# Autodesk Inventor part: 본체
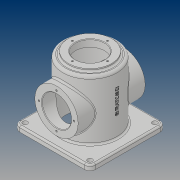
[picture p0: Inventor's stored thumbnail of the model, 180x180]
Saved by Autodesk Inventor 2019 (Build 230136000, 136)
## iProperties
Created: 2019-03
Part Number: 본체
Material: 일반
Document SubType Name: Modeling
Designer: PC312-13
Density: 1 g/cm^3
Appearance: 기본값
Author: PC312-13
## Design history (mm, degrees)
sketch "스케치1"
  geometry: C1 r 50 at (0, 0); 1 further point
  constraints: 1 centre point, 1 coincident
  dimensions: "d0" = 100 diameter of C1
extrude "돌출1" new body sketch "스케치1" distance "d1" = 120; taper "d2" = 0 deg
sketch "스케치2"
  geometry: C1 r 45 at (0, 0); 1 further point
  constraints: 1 centre point, 1 coincident
  dimensions: "d3" = 90 diameter of C1
extrude "돌출2" cut sketch "스케치2" distance "d4" = 112; taper "d5" = 0 deg
sketch "스케치3"
  geometry: L1 (-70, -70)-(70, -70); L2 (70, -70)-(70, 70); L3 (70, 70)-(-70, 70); L4 (-70, 70)-(-70, -70); L5 (-70, -70)-(70, 70); L6 (70, -70)-(-70, 70); C1 r 45 at (0, 0) reference; 1 further point
  constraints: 12 end point, 2 midpoint, 2 parallel, 1 horizontal, 1 perpendicular
  dimensions: "d6" = 140 distance of L3.end L2.end; "d7" = 140 distance of L1.end L2.end
extrude "돌출3" join sketch "스케치3" distance "d8" = 10; taper "d9" = 0 deg
sketch "스케치4"
  geometry: C1 r 40 at (0, 0); 1 further point
  constraints: 1 centre point, 1 coincident
  dimensions: "d10" = 80 diameter of C1
extrude "돌출4" join sketch "스케치4" distance "d11" = 5; taper "d12" = 0 deg
sketch "스케치5"
  geometry: C1 r 27 at (0, 0); 1 further point
  constraints: 1 centre point, 1 coincident
  dimensions: "d13" = 54 diameter of C1
extrude "돌출5" cut sketch "스케치5" extent not by distance; stored distance "d14" = 5; taper "d15" = 0 deg
node "작업 평면1"
sketch "스케치6"
  geometry: L1 (70, 0)-(-70, 0) reference; C1 r 40 at (0, 60); 2 further points
  constraints: 1 centre point, 1 midpoint, 1 vertical alignment
  dimensions: "d17" = 80 diameter of C1; "d18" = 60 distance from line of L1 C1.centre
extrude "돌출6" join sketch "스케치6" stored distance "d19" = 5; taper "d20" = 0 deg
sketch "스케치7"
  geometry: C1 r 40 at (0, 0) reference; 2 further points
  constraints: 1 vertical alignment
  dimensions: "d21" = 32.5 distance of point (0, 32.5) C1.centre
hole "구멍1" sketch "스케치7" at (0, 32.5) diameter "d22" = 3.242; stored, may be unused: countersink angle "d26" = 90 deg, drill point angle "d28" = 118 deg; dims "d23" = 8, "d24" = 4, "d25" = 2, "d27" = 10
fillet "모깎기1" dims "d32" = 10
fillet "모깎기2" dims "d33" = 5
fillet "모깎기3" dims "d34" = 3
sketch "스케치8"
  geometry: 2 further points
  constraints: 1 vertical alignment
  dimensions: "d35" = 32.5 distance of point (0, 32.5) point (0, 0)
hole "구멍2" sketch "스케치8" at (0, 32.5) diameter "d36" = 3.242; stored, may be unused: countersink angle "d40" = 90 deg, drill point angle "d42" = 118 deg; dims "d37" = 8, "d38" = 4, "d39" = 2, "d41" = 10
sketch "스케치9"
  geometry: C1 r 1.621 at (-32.5, 0) reference; C2 r 1.621 at (0, -32.5) reference; C3 r 1.621 at (32.5, 0) reference; C4 r 1.621 at (0, 32.5) reference; C5 r 40 at (0, 0) reference; C6 r 27 at (0, 0); 1 further point
  constraints: 1 centre point, 1 coincident
  dimensions: "d46" = 54 diameter of C6
extrude "돌출7" cut sketch "스케치9" extent not by distance; stored distance "d47" = 0; taper "d48" = 0 deg
sketch "스케치10"
  geometry: A1 r 10 centre (-60, -60) between (-70, -60) and (-60, -70) reference; 2 further points
  constraints: 1 coincident
hole "구멍3" sketch "스케치10" at (-60, -60) diameter "d49" = 9; stored, may be unused: countersink angle "d53" = 90 deg, drill point angle "d55" = 0 deg; dims "d50" = 8, "d51" = 4, "d52" = 2, "d54" = 10
fillet "모깎기4" dims "d62" = 3
fillet "모깎기5" dims "d63" = 3
chamfer "모따기1" distance "d64" = 1; stored, may be unused: second distance "d65" = 2, angle "d66" = 45 deg
node "작업 평면2"
sketch "스케치11"
  geometry: L1 (0, -60)-(0, 60) reference; 3 further points
  constraints: 1 horizontal alignment, 1 midpoint, 1 other
  dimensions: "d68" = 70 distance from line of L1 point (70, 0)
feature "엠보싱1" sketch "스케치11" dims "d69" = 0.5, "d70" = 0
node "솔리드1"
pattern_circular "원형 패턴1" dims angle "d30" = 360 deg
mirror "미러1"
pattern_circular "원형 패턴2" dims angle "d44" = 360 deg
pattern_linear "직사각형 패턴1" dims "d58" = 120, "d61" = 120
node "투영된 루프1"
node "투영된 루프2"
other parameters: "d16" = 62
